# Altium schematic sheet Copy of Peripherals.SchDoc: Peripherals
size A4; Date: Not used; ApprovedBy: Not used; CheckedBy: Not used; Author: Not used; CompanyName: STMicroelectronics; DrawnBy: Not used; Engineer: Not used; Organization: Not used; Address1: Not used; Address2: Not used; Address3: Not used; Address4: Not used; DocumentNumber: Not used; Revision: Not used; SheetNumber: 13; SheetTotal: 17
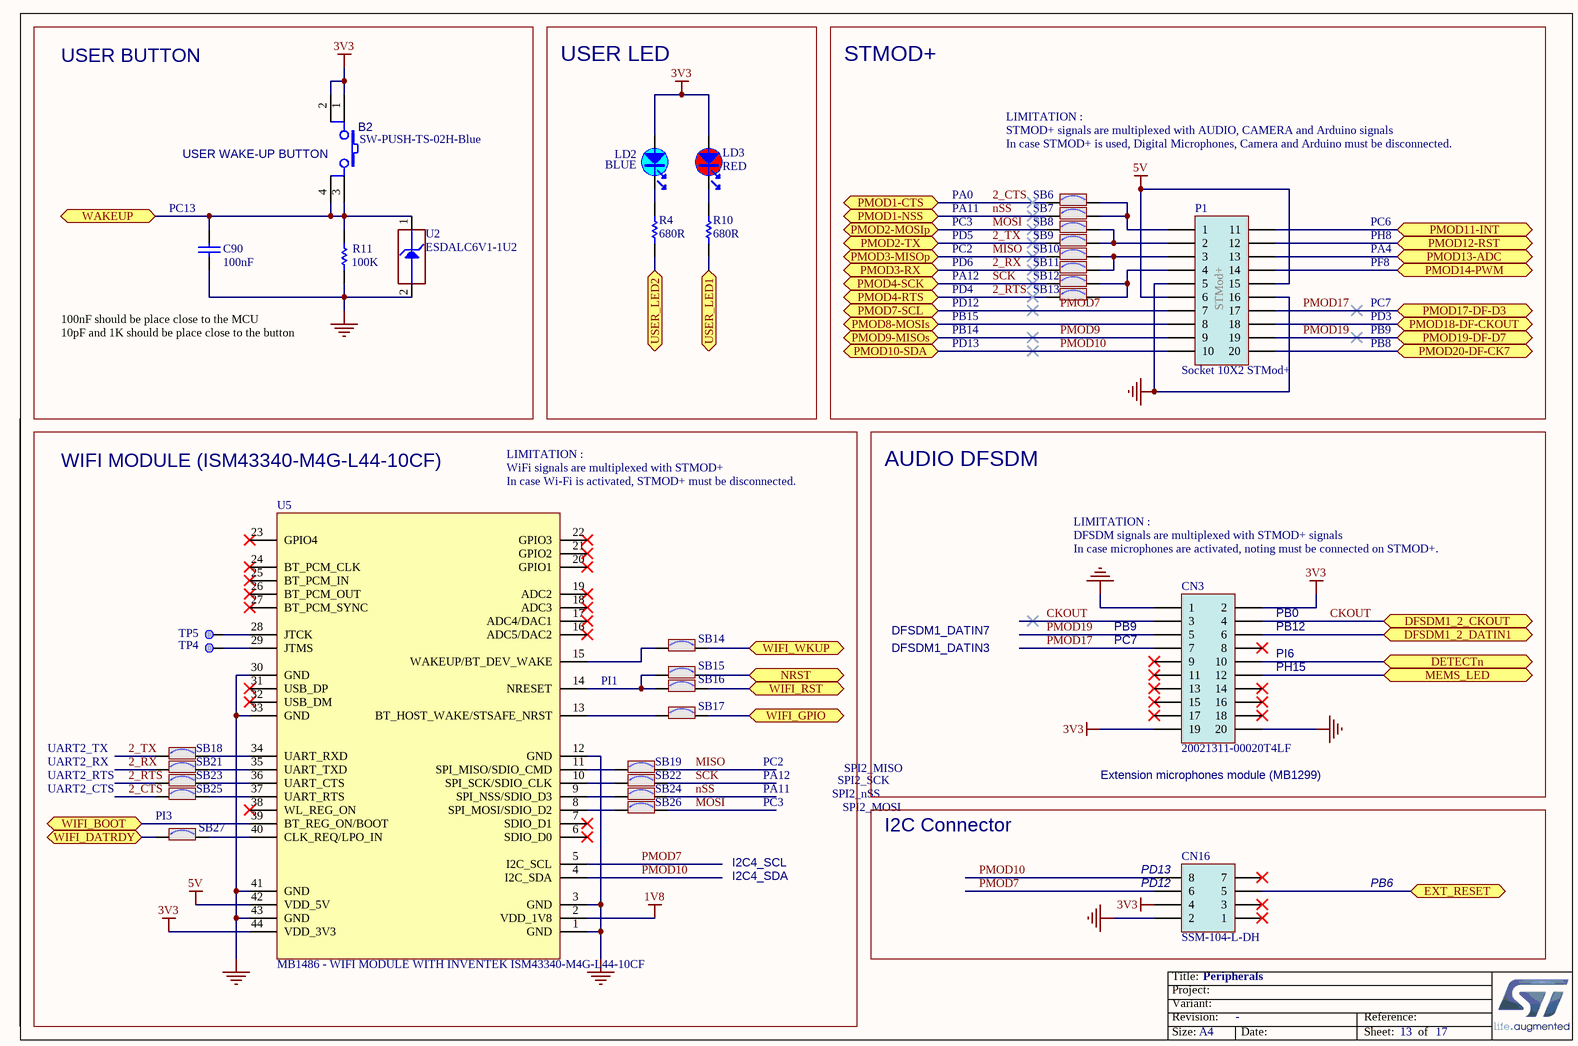
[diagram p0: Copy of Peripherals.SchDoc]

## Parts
B2  SW-PUSH-TS-02H-Blue  [SWI_JIUBABA_C-TS-02H-2-5-B-V-T_R_BLUE]
C90  value 100nF  [C0402]  (hidden comment: Capacitor)
CN3  value 20021311-00020T4LF  [CON_FCI_20021311-XXX20XXLF]  (hidden comment: Socket 10x2)
CN16  value SSM-104-L-DH  [CON_SAMTEC_SSM-104-L-DH]  (hidden comment: Socket 4x2)
LD2  value BLUE  [LED_0603_OSRAM_LB-Q39G-L2OO-35-1_BLUE_1A2K_H0P4]  (hidden comment: LED_blue)
LD3  value RED  [LED_0603_VISHAY_VLMS1300-GS08_RED_1A2K_H0P8]  (hidden comment: LED_red)
P1  Socket 10X2 STMod+  [CON_SAMTEC_SQT-110-01-F-D-RA__STMOD+]
R4  value 680R  [R0603]  (hidden comment: Resistor)
R10  value 680R  [R0603]  (hidden comment: Resistor)
R11  value 100K  [R0402]  (hidden comment: Resistor)
SB6  SB_ON  [SOLDER-BRIDGE_R0603-0R]  (value not drawn)
SB7  SB_ON  [SOLDER-BRIDGE_R0603-0R]  (value not drawn)
SB8  SB_ON  [SOLDER-BRIDGE_R0603-0R]  (value not drawn)
SB9  SB_ON  [SOLDER-BRIDGE_R0603-0R]  (value not drawn)
SB10  SB_ON  [SOLDER-BRIDGE_R0603-0R]  (value not drawn)
SB11  SB_ON  [SOLDER-BRIDGE_R0603-0R]  (value not drawn)
SB12  SB_ON  [SOLDER-BRIDGE_R0603-0R]  (value not drawn)
SB13  SB_ON  [SOLDER-BRIDGE_R0603-0R]  (value not drawn)
SB14  SB_ON  [SOLDER-BRIDGE_R0603-0R]  (value not drawn)
SB15  SB_ON  [SOLDER-BRIDGE_R0603-0R]  (value not drawn)
SB16  SB_ON  [SOLDER-BRIDGE_R0603-0R]  (value not drawn)
SB17  SB_ON  [SOLDER-BRIDGE_R0603-0R]  (value not drawn)
SB18  SB_ON  [SOLDER-BRIDGE_R0603-0R]  (value not drawn)
SB19  SB_ON  [SOLDER-BRIDGE_R0603-0R]  (value not drawn)
SB21  SB_ON  [SOLDER-BRIDGE_R0603-0R]  (value not drawn)
SB22  SB_ON  [SOLDER-BRIDGE_R0603-0R]  (value not drawn)
SB23  SB_ON  [SOLDER-BRIDGE_R0603-0R]  (value not drawn)
SB24  SB_ON  [SOLDER-BRIDGE_R0603-0R]  (value not drawn)
SB25  SB_ON  [SOLDER-BRIDGE_R0603-0R]  (value not drawn)
SB26  SB_ON  [SOLDER-BRIDGE_R0603-0R]  (value not drawn)
SB27  SB_ON  [SOLDER-BRIDGE_R0603-0R]  (value not drawn)
TP4  Test Point  [TP_SMD_0-6MM]  (value not drawn)  (no BOM)
TP5  Test Point  [TP_SMD_0-6MM]  (value not drawn)  (no BOM)
U2  value ESDALC6V1-1U2  [ESD_ST0201]  (hidden comment: ESD-TRANSIL)
U5  value MB1486 - WIFI MODULE WITH INVENTEK ISM43340-M4G-L44-10CF  [MOD_WIFI_INVENTEK_ISM43362]  (hidden comment: WIFI MODULE INTERPOSER)

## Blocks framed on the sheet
USER BUTTON: B2 C90 R11 U2
USER LED: LD2 LD3 R4 R10
STMOD+: P1 SB6-SB13
WIFI MODULE (ISM43340-M4G-L44-10CF): SB14-SB19 SB21-SB27 TP4 TP5 U5
AUDIO DFSDM: CN3
I2C Connector: CN16

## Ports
DETECTn, DFSDM1_2_CKOUT, DFSDM1_2_DATIN1, EXT_RESET, MEMS_LED, NRST, PMOD1-CTS, PMOD1-NSS, PMOD2-MOSIp, PMOD2-TX, PMOD3-MISOp, PMOD3-RX, PMOD4-RTS, PMOD4-SCK, PMOD7-SCL, PMOD8-MOSIs, PMOD9-MISOs, PMOD10-SDA, PMOD11-INT, PMOD12-RST, PMOD13-ADC, PMOD14-PWM, PMOD17-DF-D3, PMOD18-DF-CKOUT, PMOD19-DF-D7, PMOD20-DF-CK7, USER_LED1, USER_LED2, WAKEUP, WIFI_BOOT, WIFI_DATRDY, WIFI_GPIO, WIFI_RST, WIFI_WKUP

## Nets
1V8: U5.2(VDD_1V8)
3V3: B2.1 B2.2 CN3.2 CN3.19 CN16.4 LD2.1 LD3.1 U5.44(VDD_3V3)
5V: P1.6 P1.15 U5.42(VDD_5V)
GND: C90.1 CN3.1 CN3.20 CN16.2 P1.5 P1.16 R11.1 U2.2(GND) U5.1(GND) U5.3(GND) U5.12(GND) U5.30(GND) U5.33(GND) U5.41(GND) U5.43(GND)
2_CTS: SB6.1 SB25.2 ; port PMOD1-CTS
2_RTS: SB13.1 SB23.2 ; port PMOD4-RTS
2_RX: SB11.1 SB21.2 ; port PMOD3-RX
2_TX: SB9.1 SB18.2 ; port PMOD2-TX
CKOUT: CN3.3 CN3.4 ; port DFSDM1_2_CKOUT
DETECTn: CN3.10 ; port DETECTn
DFSDM1_2_DATIN1: CN3.6 ; port DFSDM1_2_DATIN1
EXT_RESET: CN16.5 ; port EXT_RESET
MEMS_LED: CN3.12 ; port MEMS_LED
MISO: SB10.1 SB19.1 ; port PMOD3-MISOp
MOSI: SB8.1 SB26.1 ; port PMOD2-MOSIp
NRST: SB15.2 ; port NRST
nSS: SB7.1 SB24.1 ; port PMOD1-NSS
PMOD7: CN16.6 P1.7 U5.5(I2C_SCL) ; port PMOD7-SCL
PMOD8-MOSIs: P1.8 ; port PMOD8-MOSIs
PMOD9: P1.9 ; port PMOD9-MISOs
PMOD10: CN16.8 P1.10 U5.4(I2C_SDA) ; port PMOD10-SDA
PMOD11-INT: P1.11 ; port PMOD11-INT
PMOD12-RST: P1.12 ; port PMOD12-RST
PMOD13-ADC: P1.13 ; port PMOD13-ADC
PMOD14-PWM: P1.14 ; port PMOD14-PWM
PMOD17: CN3.7 P1.17 ; port PMOD17-DF-D3
PMOD18-DF-CKOUT: P1.18 ; port PMOD18-DF-CKOUT
PMOD19: CN3.5 P1.19 ; port PMOD19-DF-D7
PMOD20-DF-CK7: P1.20 ; port PMOD20-DF-CK7
SCK: SB12.1 SB22.1 ; port PMOD4-SCK
USER_LED1: R10.2 ; port USER_LED1
USER_LED2: R4.2 ; port USER_LED2
WAKEUP: B2.3 B2.4 C90.2 R11.2 U2.1(IO1) ; port WAKEUP
WIFI_BOOT: U5.39(BT_REG_ON/BOOT) ; port WIFI_BOOT
WIFI_DATRDY: SB27.1 ; port WIFI_DATRDY
WIFI_GPIO: SB17.2 ; port WIFI_GPIO
WIFI_RST: SB16.2 ; port WIFI_RST
WIFI_WKUP: SB14.2 ; port WIFI_WKUP
NetLD2_2: LD2.2 R4.1
NetLD3_2: LD3.2 R10.1
NetP1_1: P1.1 SB6.2 SB7.2
NetP1_2: P1.2 SB8.2 SB9.2
NetP1_3: P1.3 SB10.2 SB11.2
NetP1_4: P1.4 SB12.2 SB13.2
NetSB14_1: SB14.1 U5.15(WAKEUP/BT_DEV_WAKE)
NetSB15_1: SB15.1 SB16.1 U5.14(NRESET)
NetSB17_1: SB17.1 U5.13(BT_HOST_WAKE/STSAFE_NRST)
NetSB18_1: SB18.1 U5.34(UART_RXD)
NetSB19_2: SB19.2 U5.11(SPI_MISO/SDIO_CMD)
NetSB21_1: SB21.1 U5.35(UART_TXD)
NetSB22_2: SB22.2 U5.10(SPI_SCK/SDIO_CLK)
NetSB23_1: SB23.1 U5.36(UART_CTS)
NetSB24_2: SB24.2 U5.9(SPI_NSS/SDIO_D3)
NetSB25_1: SB25.1 U5.37(UART_RTS)
NetSB26_2: SB26.2 U5.8(SPI_MOSI/SDIO_D2)
NetSB27_2: SB27.2 U5.40(CLK_REQ/LPO_IN)
NetTP4_1: TP4.1 U5.29(JTMS)
NetTP5_1: TP5.1 U5.28(JTCK)

Not connected (* = marked no-connect by the designer): CN3 8* 9* 11* 13* 14* 15* 16* 17* 18*; CN16 1* 3* 7*; U5 6(SDIO_D0)* 7(SDIO_D1)* 16(ADC5/DAC2)* 17(ADC4/DAC1)* 18(ADC3)* 19(ADC2)* 20(GPIO1)* 21(GPIO2)* 22(GPIO3)* 23(GPIO4)* 24(BT_PCM_CLK)* 25(BT_PCM_IN)* 26(BT_PCM_OUT)* 27(BT_PCM_SYNC)* 31(USB_DP)* 32(USB_DM)* 38(WL_REG_ON)*

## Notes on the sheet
- (near B2) USER WAKE-UP BUTTON
- LIMITATION :
  STMOD+ signals are multiplexed with AUDIO, CAMERA and Arduino signals
  In case STMOD+ is used, Digital Microphones, Camera and Arduino must be disconnected.
- (near C90) PC13
- PA0
- PC3
- PD5
- PC2
- PA11
- PC6
- PH8
- PA4
- PD6
- PA12
- PD12
- PB15
- PD4
- PF8
- PC7
- PD3
- 100nF should be place close to the MCU
  10pF and 1K should be place close to the button
- PD13
- PB14
- PB9
- PB8
- LIMITATION :
  WiFi signals are multiplexed with STMOD+
  In case Wi-Fi is activated, STMOD+ must be disconnected.
- DFSDM1_DATIN3
- DFSDM1_DATIN7
- (near CN3) LIMITATION :
  DFSDM signals are multiplexed with STMOD+ signals
  In case microphones are activated, noting must be connected on STMOD+.
- (near CN3) PB9
- (near CN3) PC7
- (near CN3) PB0
- (near CN3) PB12
- (near CN3) PI6
- PI1
- (near CN3) PH15
- UART2_TX
- UART2_RX
- UART2_RTS
- UART2_CTS
- SPI2_nSS
- SPI2_SCK
- SPI2_MISO
- (near CN3) Extension microphones module (MB1299)
- PI3
- SPI2_MOSI
- I2C4_SCL
- I2C4_SDA
- (near CN16) PD13
- (near CN16) PD12
- PB6

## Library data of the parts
B2 = MCD-00172: Switch HW SMD blue; Part_Type: Misc; Manufacturer_Part_Number: C-TS-02H-2.5-B-V-T/R BLUE; Manufacturer: JIUBABA; Provided_By: SUBCO
C90 = MCD-00006: Capacitor, MLCC, 100nF, 16V, X7R, 10%, 0402, T=0.5mm; Manufacturer_Part_Number: CC0402KRX7R7BB104; Manufacturer: YAGEO; Alternate_Manufacturer_Part_Number: GCM155R71C104KA55D; Alternate_Manufacturer: MURATA; Provided_By: SUBCO
CN3 = MCD-00147: Socket for MB1299, 10x2, 1.27mm, VR, TH, Height 4.30mm/2.40mm; Part_Type: Connector; Manufacturer: FCI; Alternate_Manufacturer_Part_Number: 234220S1410; Alternate_Manufacturer: JIUBABA; Provided_By: SUBCO
CN16 = MCD-00131: Socket, 4x2, 2.54mm, RA, SMT, Height 5.72mm; Manufacturer: SAMTEC; Part_Type: Connector; Alternate_Manufacturer_Part_Number: F206A-2x04MGF-LA; Alternate_Manufacturer: JIUBABA; Provided_By: SUBCO
LD2 = MCD-00585: LED Blue, 0603 SMD, Forward Voltage Min=2,8V, Max=3,8V; Manufacturer_Part_Number: LB Q39G-L2OO-35-1; Manufacturer: OSRAM OPTO SEMICONDUCTORS; Part_Type: Display; Alternate_Manufacturer_Part_Number: 19-217-BHC-ZL1M2RY-3T-V4; Alternate_Manufacturer: EVERLIGHT; Order_Code_RS: 9148643; Provided_By: SUBCO
LD3 = MCD-00587: LED Red, 0603 SMD, 2V Forward Voltage; Manufacturer_Part_Number: VLMS1300-GS08; Manufacturer: VISHAY; Alternate_Manufacturer_Part_Number: LS Q976-NR-1; Alternate_Manufacturer: OSRAM OPTO SEMICONDUCTORS; Part_Type: Display; Provided_By: SUBCO
P1 = MCD-00309: Socket 10x2, 2.00mm, RA, TH, Height 6.35mm/2.29mm; Part_Type: Connector; Manufacturer_Part_Number: SQT-110-01-F-D-RA; Manufacturer: SAMTEC; Alternate_Manufacturer_Part_Number: FH200020C-12300; Alternate_Manufacturer: JIUBABA; Provided_By: SUBCO
R4 R10 = MCD-00508: Resistor,680R,0603,1%,1/10W; Manufacturer_Part_Number: RC0603FR-07680RL; Manufacturer: YAGEO; Provided_By: SUBCO
R11 = MCD-00059: Resistor,100K,0402,1%,1/16W; Manufacturer_Part_Number: RC0402FR-07100KL; Manufacturer: YAGEO; Alternate_Manufacturer_Part_Number: RT0402FRE07100KL; Provided_By: SUBCO
SB6-SB19 SB21-SB27 = MCD-00071: Solder Bridge ON; Part_Type: Mechanical; Manufacturer_Part_Number: RC0603JR-070RL; Manufacturer: YAGEO; Provided_By: SUBCO
TP4 TP5 = MCD-00631: Test Point 0.6mm; Part_Type: Mechanical
U2 = MCD-00170: ESD protection 6V1; Part_Type: Diode; Manufacturer: STMICROELECTRONICS; BMS_Part_Number: 9151132; Provided_By: SUBCO with ST control
U5 = MCD-01999: 44 pins Interposer for WIFI module (MB1486 module is with INVENTEK ISM43340-M4G-L44-10CF); Part_Type: Misc; Manufacturer: STMICROELECTRONICS; ECCN_US: 5A992C; Provided_By: SUBCO with ST control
